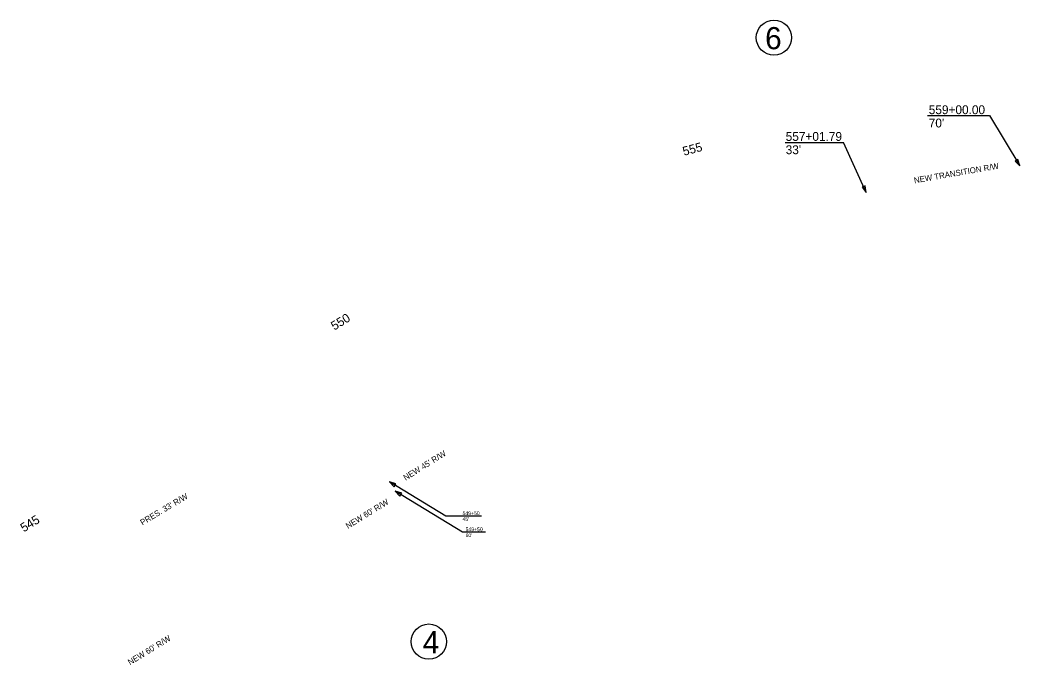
# Model space of a CAD drawing. Extents: x -64038 to -60878, y 1838 to 8465.
# Drawn here: x -63844 to -62489, y 6993 to 7866 of the extents above; entities that cross this region are included whole.
import ezdxf

# ---------------------------------------------------------------- set-up
doc = ezdxf.new("R2010")
doc.units = 0
for name, color, linetype in [('Level 21', 7, 'Continuous'), ('Level 24', 7, 'Continuous'), ('Level 25', 7, 'Continuous'), ('Level 33', 7, 'Continuous')]:
    doc.layers.add(name, color=color, linetype=linetype)

msp = doc.modelspace()

# ---------------------------------------------------------------- linework, layer by layer
at = {"layer": 'Level 24'}
for p, q in [((-62491.6, 7677.6), (-62495.5, 7675.3)), ((-62495.5, 7675.3), (-62488.9, 7668.7)), ((-62488.9, 7668.7), (-62491.6, 7677.6)), ((-62698.7, 7641.8), (-62702.8, 7640)), ((-62697.1, 7632.7), (-62698.7, 7641.8)), ((-62702.8, 7640), (-62697.1, 7632.7)), ((-63343.2, 7241), (-63336.7, 7234.4)), ((-63334.4, 7238.2), (-63343.2, 7241)), ((-63336.7, 7234.4), (-63334.4, 7238.2)), ((-63335.4, 7228.2), (-63328.8, 7221.6)), ((-63326.5, 7225.5), (-63335.4, 7228.2)), ((-63328.8, 7221.6), (-63326.5, 7225.5))]:
    msp.add_line(p, q, dxfattribs=at)
at = {"layer": 'Level 25'}
for centre in [(-62822.2, 7842.5), (-63289.7, 7024.6)]:
    msp.add_circle(centre, 23.9, dxfattribs=at)
at = {"layer": 'Level 33'}
for p, q in [((-62614.4, 7736.9), (-62530.2, 7736.9)), ((-62530.2, 7736.9), (-62488.9, 7668.7)), ((-62807, 7700.7), (-62727.9, 7700.7)), ((-62697.1, 7632.7), (-62727.9, 7700.7)), ((-63266.8, 7194.6), (-63343.2, 7241)), ((-63243.9, 7172.8), (-63335.4, 7228.2)), ((-63218.2, 7194.6), (-63266.8, 7194.6)), ((-63213, 7172.8), (-63243.9, 7172.8))]:
    msp.add_line(p, q, dxfattribs=at)

# ---------------------------------------------------------------- texts
at = {"layer": 'Level 21'}
for s, rotation, p in [('555', 14.8036, (-62944.1, 7682.5)), ('550', 31.6333, (-63417.7, 7445.7)), ('545', 31.6333, (-63838.4, 7172.5))]:
    msp.add_text(s, height=12, rotation=rotation, dxfattribs=at).set_placement(p)
at = {"layer": 'Level 25'}
for s, p in [('6', (-62834.1, 7826.8)), ('4', (-63297.9, 7008.8))]:
    msp.add_text(s, height=30, dxfattribs=at).set_placement(p)
at = {"layer": 'Level 33'}
for s, height, p in [('559+00.00', 12, (-62612.5, 7738.9)), ("70'", 12, (-62612.5, 7720.9)), ('557+01.79', 12, (-62806.3, 7702.7)), ("33'", 12, (-62806.3, 7684.7)), ('549+50', 5, (-63244.1, 7196)), ("45'", 5, (-63244.1, 7188)), ('549+50', 5, (-63239.9, 7174.2)), ("60'", 5, (-63239.9, 7166.2))]:
    msp.add_text(s, height=height, dxfattribs=at).set_placement(p)
for s, rotation, p in [('NEW TRANSITION R/W', 9.8615, (-62631.8, 7645.2)), ("NEW 45' R/W", 32.0859, (-63321.1, 7242.4)), ("PRES. 33' R/W", 30.8765, (-63677.7, 7181.8)), ("NEW 60' R/W", 31.6334, (-63399.2, 7177.1)), ("NEW 60' R/W", 31.6334, (-63694.4, 6992.5))]:
    msp.add_text(s, height=8, rotation=rotation, dxfattribs=at).set_placement(p)

doc.saveas('drawing.dxf')
